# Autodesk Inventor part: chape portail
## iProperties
Shininess: 20.0
Length Units: 11269
Angle Units: 11279
Time Units: 11290
Mass Units: 11283
Length Display Precision: 3
Angle Display Precision: 2
Compacted: True
Created: 2002-09
Part Number: chape portail
Material: Par défaut
Document SubType Name: Modélisation
Designer: thchene
Density: 0.0
Volumn: 0.0
Area: 0.0
PropertySet Name: Model Information
Control State: 0
Master: False
Checked Out: False
Author: thchene
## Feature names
1. Extrusion1
2. Extrusion2
3. Congé1 [Fillet]
4. Perçage1 [Hole]
5. Congé2 [Fillet]
6. Symétrie1 [Mirror]
